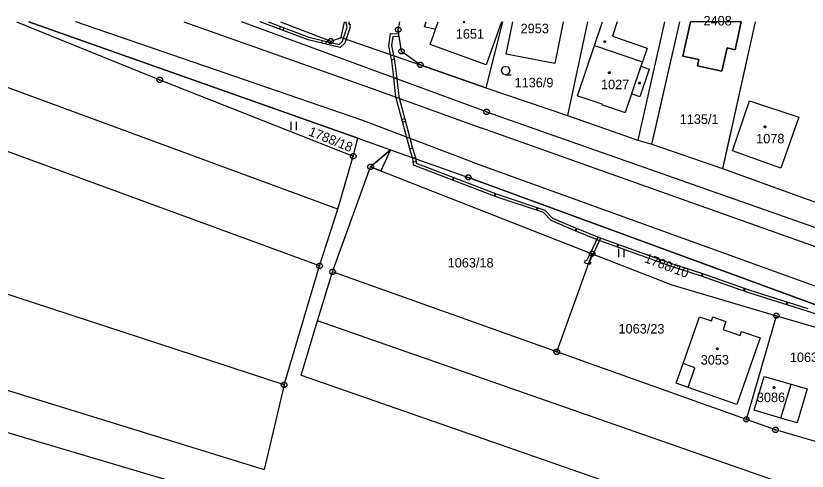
# Model space of a CAD drawing. Extents: x -777309 to -774195, y -1144706 to -1143600.
# Drawn here: x -775900.8 to -775759.1, y -1143980.5 to -1143898.9 of the extents above; entities that cross this region are included whole.
import ezdxf

# ---------------------------------------------------------------- set-up
doc = ezdxf.new("R2010")
doc.units = 0
for name, color, linetype in [('1', 7, 'Continuous'), ('11', 7, 'Continuous'), ('12', 7, 'Continuous'), ('13', 7, 'Continuous'), ('2', 7, 'Continuous'), ('3', 7, 'Continuous'), ('4', 7, 'Continuous'), ('5', 7, 'Continuous'), ('8', 7, 'Continuous')]:
    doc.layers.add(name, color=color, linetype=linetype)

msp = doc.modelspace()

# ---------------------------------------------------------------- linework, layer by layer
at = {"layer": '1'}
for p, q in [((-775846.45, -1143943.71), (-775965.55, -1143900)), ((-775843.2, -1143933.51), (-775934.15, -1143900)), ((-775900.7, -1143900), (-775875.06, -1143910.38)), ((-775839.59, -1143920.84), (-775898.5, -1143900)), ((-775816.55, -1143916.09), (-775860.41, -1143900)), ((-775853.45, -1143900), (-775844.45, -1143903.42)), ((-775842.6, -1143902.76), (-775841.98, -1143900)), ((-775832.37, -1143901.38), (-775832.08, -1143900)), ((-775827.67, -1143900.87), (-775827.38, -1143900)), ((-775825.7, -1143901.37), (-775827.67, -1143900.87)), ((-775813.71, -1143900), (-775816.68, -1143911.78)), ((-775813.9, -1143900), (-775816.63, -1143907.66)), ((-775813.01, -1143905.74), (-775811.83, -1143900)), ((-775802.81, -1143900), (-775804.35, -1143907.46)), ((-775798.46, -1143900), (-775802.05, -1143916.78)), ((-775784.71, -1143900), (-775789.47, -1143921.2)), ((-775786.97, -1143921.91), (-775781.97, -1143900)), ((-775781.41, -1143906.11), (-775780.04, -1143900)), ((-775768.44, -1143900), (-775774.28, -1143926.22)), ((-775770.94, -1143900), (-775772.04, -1143904.99)), ((-775831.79, -1143905.26), (-775832.37, -1143901.38)), ((-775826.67, -1143904.06), (-775825.7, -1143901.37)), ((-775844.45, -1143903.42), (-775842.6, -1143902.76)), ((-775842.6, -1143902.76), (-775828.41, -1143907.69)), ((-775816.63, -1143907.66), (-775826.67, -1143904.06)), ((-775773.49, -1143904.65), (-775774.44, -1143908.83)), ((-775772.04, -1143904.99), (-775773.49, -1143904.65)), ((-775828.41, -1143907.69), (-775831.79, -1143905.26)), ((-775804.35, -1143907.46), (-775813.01, -1143905.74)), ((-775778.53, -1143906.75), (-775781.41, -1143906.11)), ((-775816.68, -1143911.78), (-775828.41, -1143907.69)), ((-775778.76, -1143907.84), (-775778.53, -1143906.75)), ((-775774.44, -1143908.83), (-775778.76, -1143907.84)), ((-775875.06, -1143910.38), (-775840.42, -1143924.04)), ((-775816.68, -1143911.78), (-775802.05, -1143916.78)), ((-775816.55, -1143916.09), (-775746.05, -1143940.95)), ((-775802.05, -1143916.78), (-775789.47, -1143921.2)), ((-775840.42, -1143924.04), (-775839.59, -1143920.84)), ((-775839.59, -1143920.84), (-775833.75, -1143922.91)), ((-775789.47, -1143921.2), (-775786.97, -1143921.91)), ((-775786.97, -1143921.91), (-775774.28, -1143926.22)), ((-775852.8, -1143965.03), (-775981.49, -1143922.88)), ((-775833.75, -1143922.91), (-775837.32, -1143925.95)), ((-775833.75, -1143922.91), (-775819.81, -1143927.84)), ((-775843.2, -1143933.51), (-775840.42, -1143924.04)), ((-775844.12, -1143944.76), (-775837.32, -1143925.95)), ((-775837.32, -1143925.95), (-775797.65, -1143941.52)), ((-775774.28, -1143926.22), (-775759.13, -1143931.76)), ((-775742.96, -1143956.04), (-775819.81, -1143927.84)), ((-775846.45, -1143943.71), (-775843.2, -1143933.51)), ((-775803.97, -1143959.09), (-775797.65, -1143941.52)), ((-775797.65, -1143941.52), (-775783.4, -1143947.11)), ((-775852.8, -1143965.03), (-775846.45, -1143943.71)), ((-775846.83, -1143953.53), (-775844.12, -1143944.76)), ((-775803.97, -1143959.09), (-775844.12, -1143944.76)), ((-775783.4, -1143947.11), (-775764.65, -1143952.63)), ((-775958.48, -1143948.68), (-775856.37, -1143980.2)), ((-775781.36, -1143961.2), (-775778.45, -1143952.8)), ((-775778.45, -1143952.8), (-775776.29, -1143953.55)), ((-775776.29, -1143953.55), (-775776.05, -1143952.84)), ((-775776.05, -1143952.84), (-775773.68, -1143953.67)), ((-775770.02, -1143971.2), (-775764.65, -1143952.63)), ((-775764.65, -1143952.63), (-775741.97, -1143959.31)), ((-775966.17, -1143954.68), (-775857.78, -1143986.72)), ((-775849.76, -1143963.3), (-775846.83, -1143953.53)), ((-775759.73, -1143983.96), (-775846.83, -1143953.53)), ((-775773.68, -1143953.67), (-775774.18, -1143955.09)), ((-775774.18, -1143955.09), (-775771.12, -1143956.15)), ((-775771.12, -1143956.15), (-775770.87, -1143955.44)), ((-775770.87, -1143955.44), (-775767.55, -1143956.6)), ((-775767.55, -1143956.6), (-775771.72, -1143968.53)), ((-775770.02, -1143971.2), (-775803.97, -1143959.09)), ((-775782.57, -1143964.7), (-775781.36, -1143961.2)), ((-775849.76, -1143963.3), (-775760.9, -1143994.18)), ((-775768.64, -1143969.54), (-775766.85, -1143963.5)), ((-775766.85, -1143963.5), (-775762.02, -1143964.87)), ((-775852.8, -1143965.03), (-775856.37, -1143980.2)), ((-775780.44, -1143965.47), (-775782.57, -1143964.7)), ((-775771.72, -1143968.53), (-775780.44, -1143965.47)), ((-775762.02, -1143964.87), (-775759.15, -1143965.72)), ((-775759.15, -1143965.72), (-775760.93, -1143971.82)), ((-775763.83, -1143970.96), (-775768.64, -1143969.54)), ((-775764.81, -1143973.06), (-775770.02, -1143971.2)), ((-775760.93, -1143971.82), (-775763.83, -1143970.96)), ((-775735.6, -1143981.56), (-775764.81, -1143973.06))]:
    msp.add_line(p, q, dxfattribs=at)
at = {"layer": '11'}
msp.add_line((-775770.94, -1143900), (-775780.04, -1143900), dxfattribs=at)
for points in [[(-775898.5, -1143900), (-775839.59, -1143920.84), (-775833.75, -1143922.91), (-775819.81, -1143927.84), (-775742.96, -1143956.04), (-775707.86, -1143968.03), (-775660.24, -1143979.28), (-775641.67, -1143982.56), (-775628.98, -1143984.81), (-775600, -1143989.95)], [(-775853.45, -1143900), (-775844.45, -1143903.42), (-775842.6, -1143902.76), (-775828.41, -1143907.69), (-775816.68, -1143911.78), (-775802.05, -1143916.78), (-775789.47, -1143921.2), (-775786.97, -1143921.91), (-775786.74, -1143920.91), (-775781.97, -1143900)], [(-775780.04, -1143900), (-775781.41, -1143906.11), (-775778.53, -1143906.75), (-775778.76, -1143907.84), (-775774.44, -1143908.83), (-775773.49, -1143904.65), (-775772.04, -1143904.99), (-775770.94, -1143900)], [(-775768.44, -1143900), (-775774.19, -1143925.82), (-775774.28, -1143926.22), (-775765.58, -1143929.4), (-775759.13, -1143931.76), (-775750.29, -1143934.82)]]:
    msp.add_lwpolyline(points, dxfattribs=at)
at = {"layer": '12'}
for p, q in [((-775825.7, -1143901.37), (-775825.21, -1143900)), ((-775813.9, -1143900), (-775816.63, -1143907.66)), ((-775813.01, -1143905.74), (-775811.83, -1143900)), ((-775802.81, -1143900), (-775804.35, -1143907.46)), ((-775781.41, -1143906.11), (-775780.04, -1143900)), ((-775770.94, -1143900), (-775772.04, -1143904.99)), ((-775826.67, -1143904.06), (-775825.7, -1143901.37)), ((-775816.63, -1143907.66), (-775826.67, -1143904.06)), ((-775800.27, -1143913.2), (-775797.24, -1143904.23)), ((-775797.24, -1143904.23), (-775788.65, -1143907.16)), ((-775773.49, -1143904.65), (-775774.44, -1143908.83)), ((-775772.04, -1143904.99), (-775773.49, -1143904.65)), ((-775804.35, -1143907.46), (-775813.01, -1143905.74)), ((-775778.53, -1143906.75), (-775781.41, -1143906.11)), ((-775788.91, -1143907.93), (-775790.61, -1143912.89)), ((-775788.65, -1143907.16), (-775788.91, -1143907.93)), ((-775778.76, -1143907.84), (-775778.53, -1143906.75)), ((-775774.44, -1143908.83), (-775778.76, -1143907.84)), ((-775800.27, -1143913.2), (-775799.33, -1143913.52)), ((-775799.33, -1143913.52), (-775795.9, -1143914.67)), ((-775790.61, -1143912.89), (-775791.75, -1143916.22)), ((-775795.9, -1143914.67), (-775795.95, -1143914.81)), ((-775795.95, -1143914.81), (-775791.75, -1143916.22)), ((-775772.51, -1143923.09), (-775769.44, -1143914.15)), ((-775769.44, -1143914.15), (-775760.61, -1143917.03)), ((-775760.61, -1143917.03), (-775763.85, -1143926.2)), ((-775763.85, -1143926.2), (-775772.51, -1143923.09)), ((-775781.36, -1143961.2), (-775778.45, -1143952.8)), ((-775778.45, -1143952.8), (-775776.29, -1143953.55)), ((-775776.29, -1143953.55), (-775776.05, -1143952.84)), ((-775776.05, -1143952.84), (-775773.68, -1143953.67)), ((-775773.68, -1143953.67), (-775774.18, -1143955.09)), ((-775774.18, -1143955.09), (-775771.12, -1143956.15)), ((-775771.12, -1143956.15), (-775770.87, -1143955.44)), ((-775770.87, -1143955.44), (-775767.55, -1143956.6)), ((-775767.55, -1143956.6), (-775771.72, -1143968.53)), ((-775779.26, -1143961.95), (-775781.36, -1143961.2)), ((-775780.44, -1143965.47), (-775779.26, -1143961.95)), ((-775768.64, -1143969.54), (-775766.85, -1143963.5)), ((-775766.85, -1143963.5), (-775762.02, -1143964.87)), ((-775771.72, -1143968.53), (-775780.44, -1143965.47)), ((-775763.83, -1143970.96), (-775762.02, -1143964.87)), ((-775763.83, -1143970.96), (-775768.64, -1143969.54))]:
    msp.add_line(p, q, dxfattribs=at)
at = {"layer": '13'}
for p, q in [((-775853.62, -1143901.28), (-775853.45, -1143900.82)), ((-775840.84, -1143900.51), (-775841.32, -1143900.35)), ((-775852.86, -1143901.03), (-775853.03, -1143901.5)), ((-775846.04, -1143903.79), (-775845.91, -1143903.31)), ((-775845.26, -1143903.48), (-775845.38, -1143903.96)), ((-775833.58, -1143906.79), (-775833.09, -1143906.69)), ((-775832.66, -1143910.03), (-775833.16, -1143910.08)), ((-775831.7, -1143917.44), (-775831.22, -1143917.31)), ((-775831.07, -1143917.85), (-775831.55, -1143917.97)), ((-775837.32, -1143925.95), (-775833.75, -1143922.91)), ((-775833.75, -1143922.91), (-775835.48, -1143926.67)), ((-775829.8, -1143922.61), (-775829.19, -1143924.52)), ((-775829.58, -1143925.07), (-775829.1, -1143924.93)), ((-775835.48, -1143926.67), (-775837.32, -1143925.95)), ((-775822.67, -1143928.33), (-775822.49, -1143927.86)), ((-775822.39, -1143927.89), (-775822.57, -1143928.36)), ((-775815.21, -1143931.21), (-775815.03, -1143930.74)), ((-775814.93, -1143930.79), (-775815.09, -1143931.26)), ((-775807.62, -1143933.74), (-775807.47, -1143933.27)), ((-775807.34, -1143933.31), (-775807.49, -1143933.78)), ((-775800.67, -1143937.43), (-775800.47, -1143936.97)), ((-775800.39, -1143937), (-775800.57, -1143937.46)), ((-775793.19, -1143940.27), (-775793.02, -1143939.8)), ((-775792.91, -1143939.84), (-775793.08, -1143940.31)), ((-775798.06, -1143943.47), (-775798.32, -1143943.38)), ((-775785.66, -1143942.99), (-775785.49, -1143942.52)), ((-775785.38, -1143942.55), (-775785.55, -1143943.02)), ((-775778.07, -1143945.51), (-775777.92, -1143945.03)), ((-775777.79, -1143945.08), (-775777.96, -1143945.55)), ((-775770.53, -1143948.18), (-775770.37, -1143947.71)), ((-775770.25, -1143947.74), (-775770.42, -1143948.21)), ((-775762.91, -1143950.61), (-775762.76, -1143950.13)), ((-775762.63, -1143950.17), (-775762.78, -1143950.64))]:
    msp.add_line(p, q, dxfattribs=at)
for points in [[(-775841.24, -1143900), (-775840.97, -1143900.91), (-775841.67, -1143903.08), (-775841.9, -1143903.8), (-775842.79, -1143904.6), (-775848.49, -1143903.18), (-775857.1, -1143900)], [(-775855.65, -1143900), (-775848.35, -1143902.7), (-775842.93, -1143904.06), (-775842.34, -1143903.52), (-775842.14, -1143902.92), (-775841.49, -1143900.91), (-775841.75, -1143900.03), (-775841.65, -1143900)], [(-775833.76, -1143905.83), (-775834.05, -1143904.26), (-775833.75, -1143902.09), (-775832.29, -1143902.13)], [(-775832.29, -1143902.13), (-775832.31, -1143902.63), (-775833.32, -1143902.61), (-775833.55, -1143904.24), (-775833.21, -1143906.02)], [(-775833.21, -1143906.02), (-775832.97, -1143907.29), (-775832.64, -1143910.19), (-775833.16, -1143909.99), (-775833.47, -1143907.37), (-775833.76, -1143905.83)], [(-775829.19, -1143924.52), (-775829.81, -1143924.3), (-775830.28, -1143922.75)], [(-775749.87, -1143954.92), (-775759.16, -1143951.79), (-775769.74, -1143948.46), (-775778.23, -1143945.46), (-775783.61, -1143943.73), (-775796.54, -1143939.06), (-775800.69, -1143937.42), (-775805, -1143935.56), (-775806.37, -1143934.16), (-775814.84, -1143931.35), (-775829.61, -1143925.65), (-775829.68, -1143924.74), (-775829.81, -1143924.3), (-775829.19, -1143924.52), (-775829.13, -1143925.29), (-775814.68, -1143930.87), (-775806.09, -1143933.72), (-775804.72, -1143935.14), (-775800.49, -1143936.96), (-775796.36, -1143938.6), (-775783.45, -1143943.25), (-775778.07, -1143944.98), (-775769.58, -1143947.98), (-775759, -1143951.31)]]:
    msp.add_lwpolyline(points, dxfattribs=at)
for points in [[(-775830.28, -1143922.75), (-775832.77, -1143913.43), (-775833.16, -1143909.99), (-775832.64, -1143910.19), (-775832.27, -1143913.33), (-775829.8, -1143922.61)], [(-775796.57, -1143938.5), (-775796.12, -1143938.71), (-775797.49, -1143941.58), (-775797.95, -1143941.4)], [(-775797.95, -1143941.4), (-775797.65, -1143941.52), (-775798.32, -1143943.38), (-775799, -1143943.13), (-775798.83, -1143942.66), (-775798.6, -1143942.74)], [(-775798.32, -1143943.38), (-775797.65, -1143941.52), (-775797.49, -1143941.58), (-775798.12, -1143942.92), (-775797.89, -1143943), (-775798.06, -1143943.47)]]:
    msp.add_lwpolyline(points, close=True, dxfattribs=at)
at = {"layer": '3'}
for p, q in [((-775851.58, -1143917.91), (-775851.58, -1143919.41)), ((-775850.58, -1143919.41), (-775850.58, -1143917.91)), ((-775792.92, -1143940.66), (-775792.92, -1143942.16)), ((-775791.92, -1143942.16), (-775791.92, -1143940.66))]:
    msp.add_line(p, q, dxfattribs=at)
msp.add_lwpolyline([(-775813.12, -1143909.44), (-775813.5, -1143909.34), (-775813.77, -1143909.07), (-775813.87, -1143908.7), (-775813.77, -1143908.33), (-775813.5, -1143908.06), (-775813.13, -1143907.96), (-775812.76, -1143908.06), (-775812.49, -1143908.33), (-775812.39, -1143908.71), (-775812.49, -1143909.09), (-775812.76, -1143909.36), (-775813.14, -1143909.46), (-775812.14, -1143909.46)], dxfattribs=at)
at = {"layer": '4'}
for p, q in [((-775838.68, -1143917.66), (-775890.12, -1143900)), ((-775870.76, -1143900), (-775837.03, -1143911.93)), ((-775825.7, -1143901.37), (-775825.21, -1143900)), ((-775797.24, -1143904.23), (-775795.81, -1143900)), ((-775793.15, -1143900), (-775794.01, -1143902.56)), ((-775794.01, -1143902.56), (-775787.78, -1143904.67)), ((-775800.27, -1143913.2), (-775797.24, -1143904.23)), ((-775797.24, -1143904.23), (-775788.65, -1143907.16)), ((-775787.78, -1143904.67), (-775788.65, -1143907.16)), ((-775788.91, -1143907.93), (-775790.61, -1143912.89)), ((-775788.65, -1143907.16), (-775788.91, -1143907.93)), ((-775788.91, -1143907.93), (-775787.42, -1143908.44)), ((-775787.42, -1143908.44), (-775789.13, -1143913.4)), ((-775837.03, -1143911.93), (-775817.37, -1143919.03)), ((-775800.27, -1143913.2), (-775799.33, -1143913.52)), ((-775799.33, -1143913.52), (-775795.9, -1143914.67)), ((-775790.61, -1143912.89), (-775791.75, -1143916.22)), ((-775789.13, -1143913.4), (-775790.61, -1143912.89)), ((-775795.9, -1143914.67), (-775795.95, -1143914.81)), ((-775795.95, -1143914.81), (-775791.75, -1143916.22)), ((-775772.51, -1143923.09), (-775769.44, -1143914.15)), ((-775769.44, -1143914.15), (-775760.61, -1143917.03)), ((-775819.06, -1143925.14), (-775838.68, -1143917.66)), ((-775760.61, -1143917.03), (-775763.85, -1143926.2)), ((-775747.13, -1143944.02), (-775817.37, -1143919.03)), ((-775763.85, -1143926.2), (-775772.51, -1143923.09)), ((-775819.06, -1143925.14), (-775749.36, -1143950.31)), ((-775779.26, -1143961.95), (-775781.36, -1143961.2)), ((-775780.44, -1143965.47), (-775779.26, -1143961.95)), ((-775763.83, -1143970.96), (-775762.02, -1143964.87))]:
    msp.add_line(p, q, dxfattribs=at)
at = {"layer": '5'}
msp.add_line((-775820.46, -1143900), (-775820.75, -1143900), dxfattribs=at)
msp.add_lwpolyline([(-775820.75, -1143900), (-775820.7, -1143900.05), (-775820.61, -1143900.08), (-775820.54, -1143900.07), (-775820.46, -1143900)], dxfattribs=at)
for points in [[(-775795.3, -1143903.4), (-775795.21, -1143903.55), (-775795.3, -1143903.7), (-775795.48, -1143903.7), (-775795.57, -1143903.55), (-775795.48, -1143903.4)], [(-775794.54, -1143908.91), (-775794.44, -1143908.93), (-775794.39, -1143909.02), (-775794.37, -1143909.08), (-775794.39, -1143909.17), (-775794.47, -1143909.24), (-775794.54, -1143909.25), (-775794.63, -1143909.22), (-775794.69, -1143909.16), (-775794.71, -1143909.08), (-775794.69, -1143908.99), (-775794.61, -1143908.92)], [(-775789.05, -1143910.76), (-775788.96, -1143910.91), (-775789.05, -1143911.06), (-775789.23, -1143911.06), (-775789.32, -1143910.91), (-775789.23, -1143910.76)], [(-775766.69, -1143918.61), (-775766.59, -1143918.63), (-775766.54, -1143918.72), (-775766.52, -1143918.78), (-775766.54, -1143918.87), (-775766.62, -1143918.94), (-775766.69, -1143918.95), (-775766.78, -1143918.92), (-775766.84, -1143918.86), (-775766.86, -1143918.78), (-775766.84, -1143918.69), (-775766.76, -1143918.62)], [(-775775.21, -1143958.37), (-775775.11, -1143958.39), (-775775.06, -1143958.48), (-775775.04, -1143958.54), (-775775.06, -1143958.63), (-775775.14, -1143958.7), (-775775.21, -1143958.71), (-775775.3, -1143958.68), (-775775.36, -1143958.62), (-775775.38, -1143958.54), (-775775.36, -1143958.45), (-775775.28, -1143958.38)], [(-775765.1, -1143965.32), (-775765, -1143965.34), (-775764.95, -1143965.43), (-775764.93, -1143965.49), (-775764.95, -1143965.58), (-775765.03, -1143965.65), (-775765.1, -1143965.66), (-775765.19, -1143965.63), (-775765.25, -1143965.57), (-775765.27, -1143965.49), (-775765.25, -1143965.4), (-775765.17, -1143965.33)]]:
    msp.add_lwpolyline(points, close=True, dxfattribs=at)
at = {"layer": '8'}
for p, q in [((-775832.49, -1143901.38), (-775832.25, -1143901.38)), ((-775844.57, -1143903.42), (-775844.33, -1143903.42)), ((-775831.91, -1143905.26), (-775831.67, -1143905.26)), ((-775828.53, -1143907.69), (-775828.29, -1143907.69)), ((-775875.18, -1143910.38), (-775874.94, -1143910.38)), ((-775816.67, -1143916.09), (-775816.43, -1143916.09)), ((-775840.54, -1143924.04), (-775840.3, -1143924.04)), ((-775837.44, -1143925.95), (-775837.2, -1143925.95)), ((-775819.93, -1143927.84), (-775819.69, -1143927.84)), ((-775797.77, -1143941.52), (-775797.53, -1143941.52)), ((-775846.57, -1143943.71), (-775846.33, -1143943.71)), ((-775844.24, -1143944.76), (-775844, -1143944.76)), ((-775764.77, -1143952.63), (-775764.53, -1143952.63)), ((-775804.09, -1143959.09), (-775803.85, -1143959.09)), ((-775852.92, -1143965.03), (-775852.68, -1143965.03)), ((-775770.14, -1143971.2), (-775769.9, -1143971.2)), ((-775764.93, -1143973.06), (-775764.69, -1143973.06))]:
    msp.add_line(p, q, dxfattribs=at)
for points in [[(-775832.22, -1143900.9), (-775831.97, -1143901.08), (-775831.87, -1143901.37), (-775831.97, -1143901.66), (-775832.22, -1143901.84), (-775832.53, -1143901.84), (-775832.78, -1143901.66), (-775832.88, -1143901.37), (-775832.78, -1143901.08), (-775832.53, -1143900.9)], [(-775844.3, -1143902.94), (-775844.05, -1143903.12), (-775843.95, -1143903.41), (-775844.05, -1143903.7), (-775844.3, -1143903.88), (-775844.61, -1143903.88), (-775844.86, -1143903.7), (-775844.96, -1143903.41), (-775844.86, -1143903.12), (-775844.61, -1143902.94)], [(-775831.64, -1143904.78), (-775831.39, -1143904.96), (-775831.29, -1143905.25), (-775831.39, -1143905.54), (-775831.64, -1143905.72), (-775831.95, -1143905.72), (-775832.2, -1143905.54), (-775832.3, -1143905.25), (-775832.2, -1143904.96), (-775831.95, -1143904.78)], [(-775828.26, -1143907.21), (-775828.01, -1143907.39), (-775827.91, -1143907.68), (-775828.01, -1143907.97), (-775828.26, -1143908.15), (-775828.57, -1143908.15), (-775828.82, -1143907.97), (-775828.92, -1143907.68), (-775828.82, -1143907.39), (-775828.57, -1143907.21)], [(-775874.91, -1143909.9), (-775874.66, -1143910.08), (-775874.56, -1143910.37), (-775874.66, -1143910.66), (-775874.91, -1143910.84), (-775875.22, -1143910.84), (-775875.47, -1143910.66), (-775875.57, -1143910.37), (-775875.47, -1143910.08), (-775875.22, -1143909.9)], [(-775816.4, -1143915.61), (-775816.15, -1143915.79), (-775816.05, -1143916.08), (-775816.15, -1143916.37), (-775816.4, -1143916.55), (-775816.71, -1143916.55), (-775816.96, -1143916.37), (-775817.06, -1143916.08), (-775816.96, -1143915.79), (-775816.71, -1143915.61)], [(-775840.27, -1143923.56), (-775840.02, -1143923.74), (-775839.92, -1143924.03), (-775840.02, -1143924.32), (-775840.27, -1143924.5), (-775840.58, -1143924.5), (-775840.83, -1143924.32), (-775840.93, -1143924.03), (-775840.83, -1143923.74), (-775840.58, -1143923.56)], [(-775837.17, -1143925.47), (-775836.92, -1143925.65), (-775836.82, -1143925.94), (-775836.92, -1143926.23), (-775837.17, -1143926.41), (-775837.48, -1143926.41), (-775837.73, -1143926.23), (-775837.83, -1143925.94), (-775837.73, -1143925.65), (-775837.48, -1143925.47)], [(-775819.66, -1143927.36), (-775819.41, -1143927.54), (-775819.31, -1143927.83), (-775819.41, -1143928.12), (-775819.66, -1143928.3), (-775819.97, -1143928.3), (-775820.22, -1143928.12), (-775820.32, -1143927.83), (-775820.22, -1143927.54), (-775819.97, -1143927.36)], [(-775797.5, -1143941.04), (-775797.25, -1143941.22), (-775797.15, -1143941.51), (-775797.25, -1143941.8), (-775797.5, -1143941.98), (-775797.81, -1143941.98), (-775798.06, -1143941.8), (-775798.16, -1143941.51), (-775798.06, -1143941.22), (-775797.81, -1143941.04)], [(-775846.3, -1143943.23), (-775846.05, -1143943.41), (-775845.95, -1143943.7), (-775846.05, -1143943.99), (-775846.3, -1143944.17), (-775846.61, -1143944.17), (-775846.86, -1143943.99), (-775846.96, -1143943.7), (-775846.86, -1143943.41), (-775846.61, -1143943.23)], [(-775843.97, -1143944.28), (-775843.72, -1143944.46), (-775843.62, -1143944.75), (-775843.72, -1143945.04), (-775843.97, -1143945.22), (-775844.28, -1143945.22), (-775844.53, -1143945.04), (-775844.63, -1143944.75), (-775844.53, -1143944.46), (-775844.28, -1143944.28)], [(-775764.5, -1143952.15), (-775764.25, -1143952.33), (-775764.15, -1143952.62), (-775764.25, -1143952.91), (-775764.5, -1143953.09), (-775764.81, -1143953.09), (-775765.06, -1143952.91), (-775765.16, -1143952.62), (-775765.06, -1143952.33), (-775764.81, -1143952.15)], [(-775803.82, -1143958.61), (-775803.57, -1143958.79), (-775803.47, -1143959.08), (-775803.57, -1143959.37), (-775803.82, -1143959.55), (-775804.13, -1143959.55), (-775804.38, -1143959.37), (-775804.48, -1143959.08), (-775804.38, -1143958.79), (-775804.13, -1143958.61)], [(-775852.65, -1143964.55), (-775852.4, -1143964.73), (-775852.3, -1143965.02), (-775852.4, -1143965.31), (-775852.65, -1143965.49), (-775852.96, -1143965.49), (-775853.21, -1143965.31), (-775853.31, -1143965.02), (-775853.21, -1143964.73), (-775852.96, -1143964.55)], [(-775769.87, -1143970.72), (-775769.62, -1143970.9), (-775769.52, -1143971.19), (-775769.62, -1143971.48), (-775769.87, -1143971.66), (-775770.18, -1143971.66), (-775770.43, -1143971.48), (-775770.53, -1143971.19), (-775770.43, -1143970.9), (-775770.18, -1143970.72)], [(-775764.66, -1143972.58), (-775764.41, -1143972.76), (-775764.31, -1143973.05), (-775764.41, -1143973.34), (-775764.66, -1143973.52), (-775764.97, -1143973.52), (-775765.22, -1143973.34), (-775765.32, -1143973.05), (-775765.22, -1143972.76), (-775764.97, -1143972.58)]]:
    msp.add_lwpolyline(points, close=True, dxfattribs=at)

# ---------------------------------------------------------------- texts
at = {"layer": '2'}
for s, p in [('2408', (-775777.7, -1143900.62)), ('2953', (-775810.45, -1143902.01)), ('1651', (-775822.06, -1143902.98)), ('1136/9', (-775811.53, -1143911.71)), ('1027', (-775796.06, -1143912.04)), ('1135/1', (-775781.96, -1143918.26)), ('1078', (-775768.27, -1143921.74)), ('1063/18', (-775823.51, -1143943.98)), ('1063/23', (-775792.92, -1143955.81)), ('3053', (-775778.2, -1143961.38)), ('1063/24', (-775762.24, -1143960.92)), ('3086', (-775768.15, -1143968.1))]:
    msp.add_text(s, height=1.7, dxfattribs=at).set_placement(p)
for s, rotation, p in [('1788/18', 338.1597, (-775848.57, -1143920.27)), ('1788/10', 339.3629, (-775788.42, -1143942.98))]:
    msp.add_text(s, height=1.7, rotation=rotation, dxfattribs=at).set_placement(p)

doc.saveas('drawing.dxf')
